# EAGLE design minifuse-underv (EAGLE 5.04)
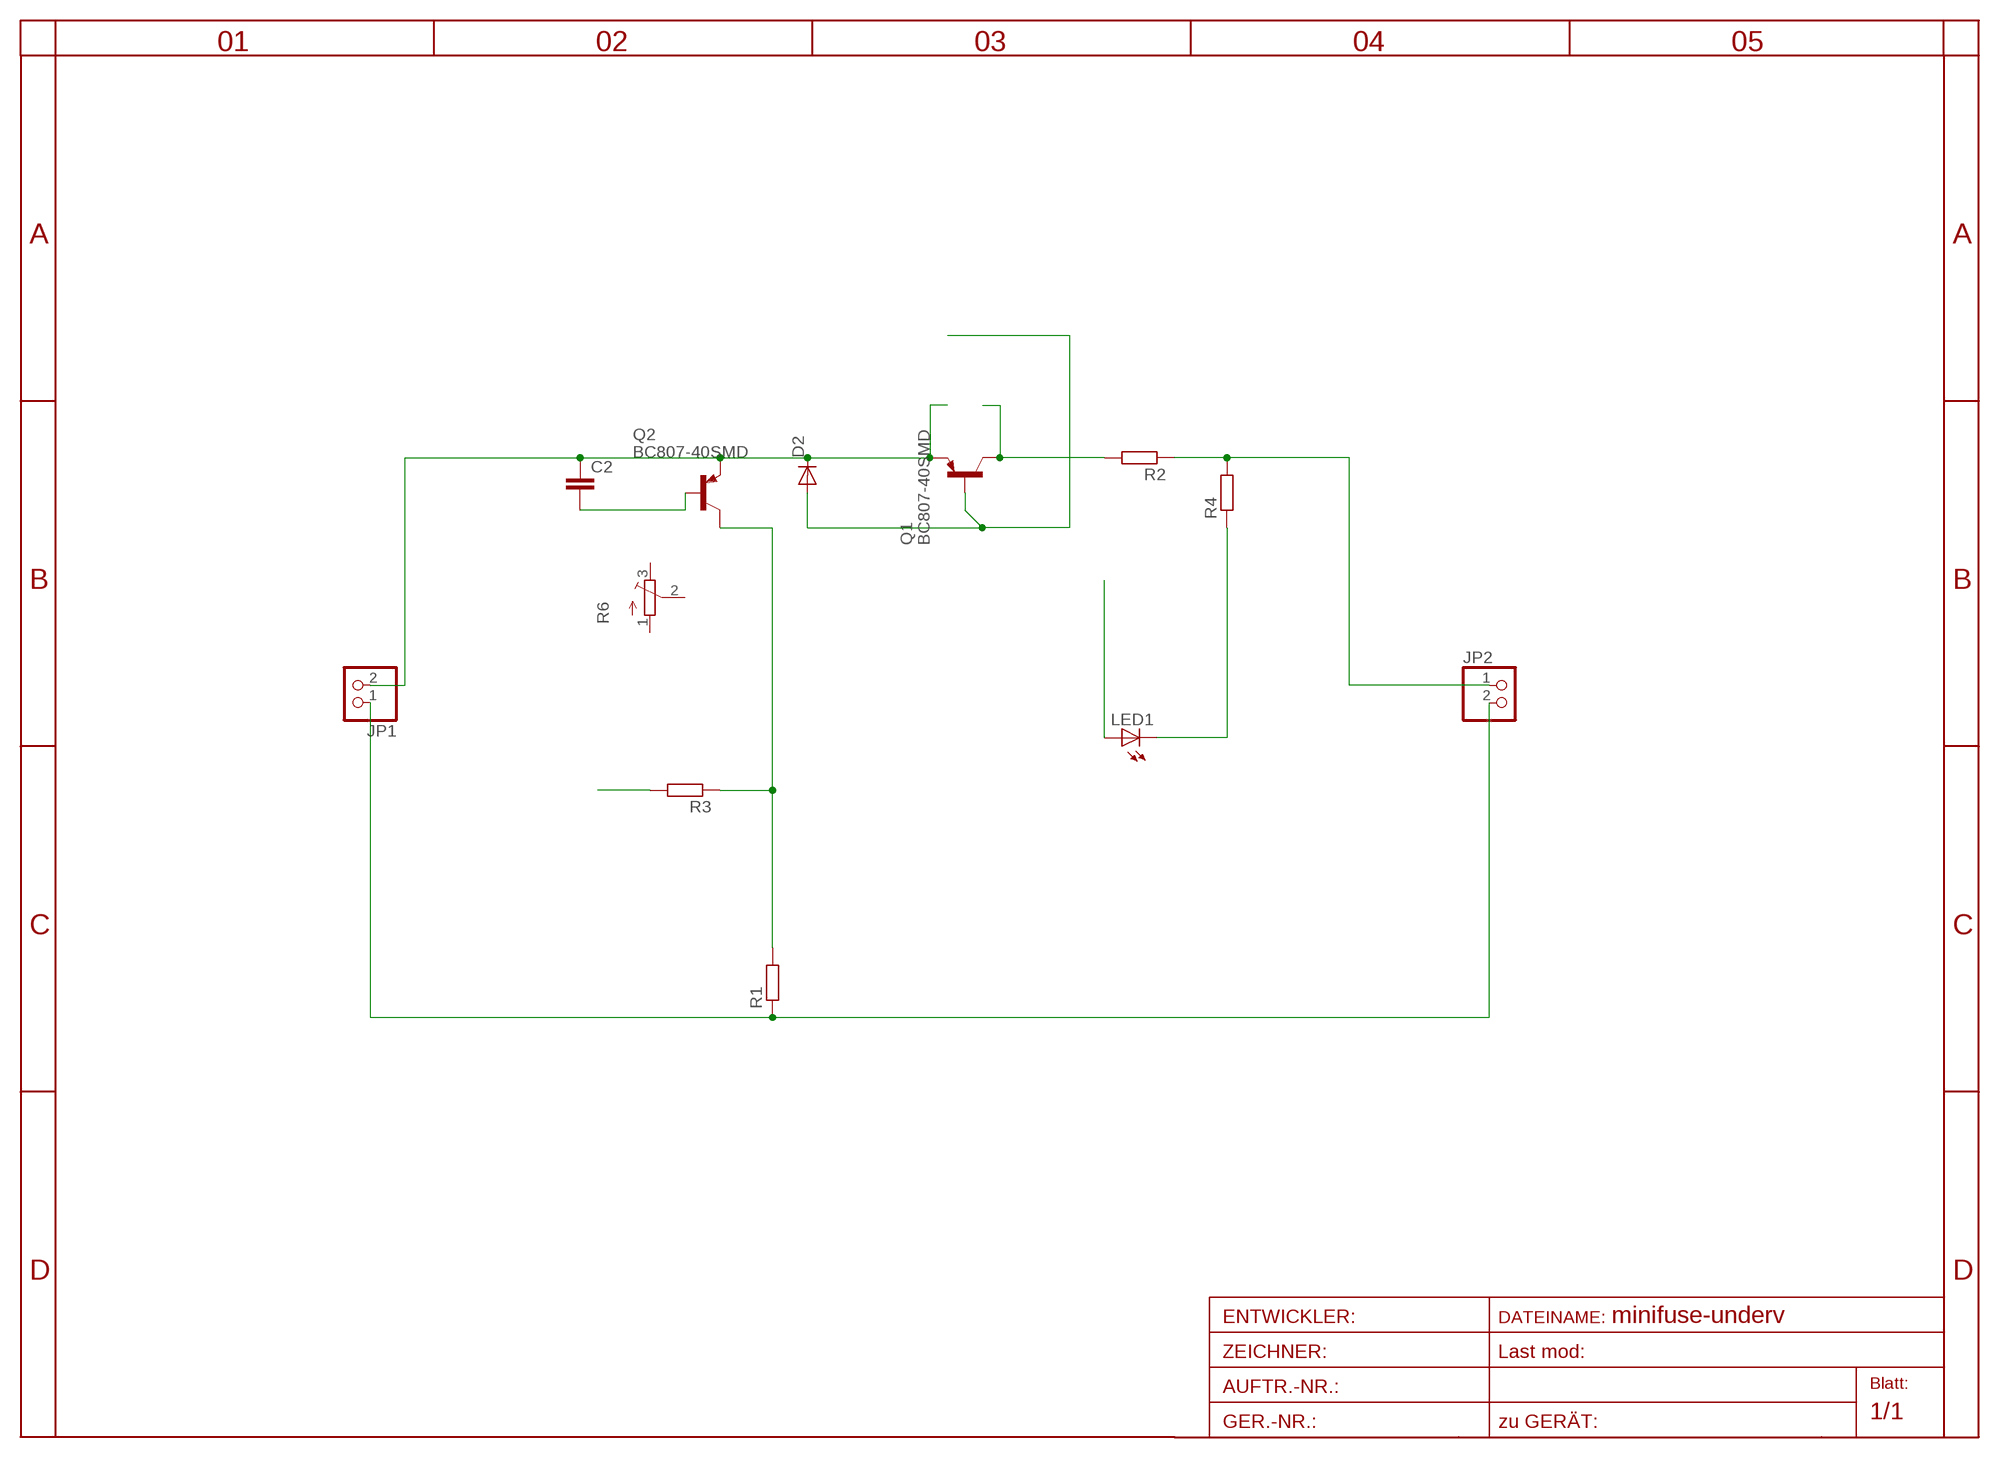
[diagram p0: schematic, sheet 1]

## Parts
C2  C-EUC0805  [C0805]
D2  DIODE-MINIMELF  [MINIMELF]
JP1  PINHD-1X2  [1X02]
JP2  PINHD-1X2  [1X02]
LED1  LEDSMT1206  [1206]
Q1  BC807-40SMD  [SOT23-BEC]
Q2  BC807-40SMD  [SOT23-BEC]
R1  R-EU_R0805  [R0805]
R2  R-EU_0204/7  [0204/7]
R3  R-EU_R0805  [R0805]
R4  R-EU_R1206  [R1206]
R6  TRIM_EU-SM-42/43A  [SM-42/43A]

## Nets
N$1: JP1.1 JP2.2 R1.1
N$2: C2.1 D2.C JP1.2 Q1.E Q2.E
N$3: LED1.A
N$4: Q2.C R1.2 R3.1
N$5: R3.2
N$6: C2.2 Q2.B
N$8: JP2.1 R2.1 R4.2
N$9: Q1.C R2.2
N$10: D2.A Q1.B
N$11: LED1.C R4.1
Unconnected: R6.1(A) R6.2(S) R6.3(E)

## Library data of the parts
C2 = rcl-2:C-EU: CAPACITOR, European symbol
D2 = diode-1:DIODE-: DIODE
JP1 JP2 = pinhead:PINHD-1X2: PIN HEADER
LED1 = led:LED: LED
Q1 Q2 = transistor-pnp:BC807*: PNP Transistror
R1-R4 = rcl-2:R-EU_: RESISTOR, European symbol
R6 = pot:TRIM_EU-: POTENTIOMETER

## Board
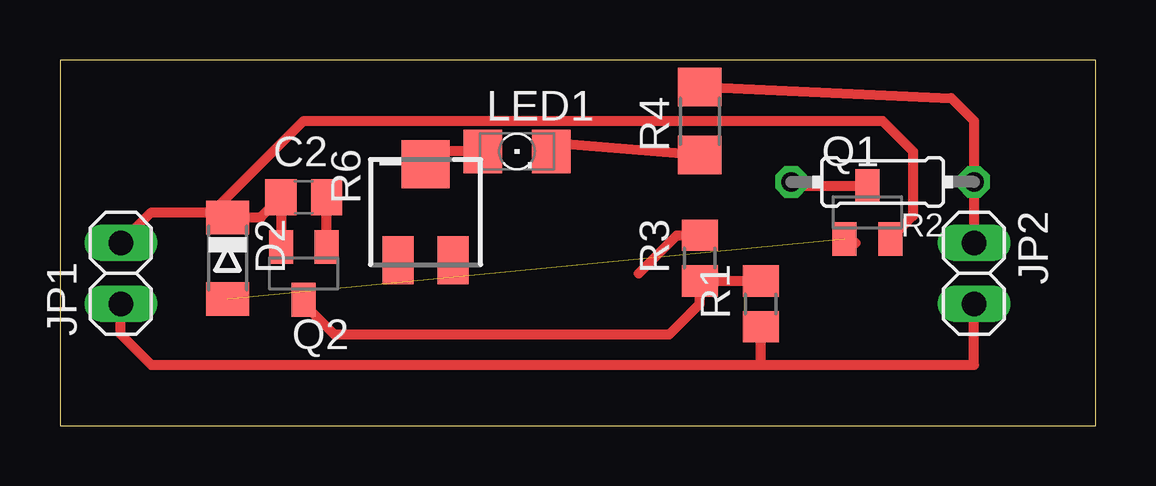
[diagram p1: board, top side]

Size 43.18 x 15.24 mm. Coordinates in mm from the lower left corner, seen from the top.
Outline: 0,0 43.18,0 43.18,15.24 0,15.24 0,0
Copper layers (1*16): Top 0.035mm / dielectric 1.5mm / Bottom 0.035mm
Design rules "default": minimum track width 10mil, minimum drill 24mil, track to track 8mil, track to pad 8mil, pad to pad 8mil, via to via 8mil, smd to smd 8mil, copper to edge 40mil, drill to drill 8mil, minimum pad ring 10mil, minimum via ring 8mil, stop-mask expansion 4mil, vias tented up to drill 0mil, thermal gap 10mil

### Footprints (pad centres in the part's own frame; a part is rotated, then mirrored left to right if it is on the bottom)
C0805 = smd 1.3 x 1.5: 1 -0.95,0; 2 0.95,0
MINIMELF = smd 1.4 x 1.8: A 1.7,0; C -1.7,0
1X02 = drill 1.016 long: 1 -1.27,0; 2 1.27,0
1206 = smd 1.6 x 1.803: A -1.422,0; C 1.422,0
SOT23-BEC = smd 1 x 1.4: B -0.95,-1.1; C 0,1.1; E 0.95,-1.1
R0805 = smd 1.3 x 1.5: 1 -0.95,0; 2 0.95,0
0204/7 = drill 0.813 octagon: 1 -3.81,0; 2 3.81,0
R1206 = smd 1.6 x 1.803: 1 -1.422,0; 2 1.422,0
SM-42/43A = smd 2 x 1.3: 1 2,1.15; 3 2,-1.15 | smd 2 x 2: 2 -2,0

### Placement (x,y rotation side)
C2  10.16,9.53 0 top
D2  6.99,6.99 270 top
JP1  2.54,6.35 90 top
JP2  38.1,6.35 270 top
LED1  19.05,11.43 0 top
Q1  33.66,8.89 0 top
Q2  10.16,6.35 180 top
R1  29.21,5.08 90 top
R2  34.29,10.16 180 top
R3  26.67,6.99 90 top
R4  26.67,12.7 90 top
R6  15.24,8.89 270 top

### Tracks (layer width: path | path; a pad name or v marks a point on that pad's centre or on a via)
N$1
  Top 0.406: JP1.1 2.54,3.81 3.81,2.54 29.21,2.54 | 29.21,2.54 33.02,2.54 38.1,2.54 JP2.2 | 29.21,2.54 R1.1
N$2
  Top 0.406: JP1.2 3.81,8.89 6.35,8.89 | 6.35,8.89 6.78,8.89 D2.C 8.37,8.69 C2.1 Q2.E | 6.35,8.89 10.16,12.7 34.29,12.7 35.56,11.43 35.56,8.74 Q1.E
N$3
  Top 0.406: LED1.A 15.24,11.43
N$4
  Top 0.406: 10.12,5.29 Q2.C 10.16,5.08 11.43,3.81 25.4,3.81 26.67,5.08 R3.1 R1.2 29.53,6.35
N$5
  Top 0.406: R3.2 25.71,7.93 24.13,6.35
N$6
  Top 0.406: Q2.B C2.2
N$8
  Top 0.406: R4.2 37.15,13.65 38.1,12.7 R2.1 JP2.1
N$9
  Top 0.406: Q1.C 30.65,9.99 R2.2
N$10  (1 unrouted)
  Top 0.406: 33.02,7.47 Q1.B 33.17,7.62
N$11
  Top 0.406: R4.1 20.79,11.75 LED1.C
